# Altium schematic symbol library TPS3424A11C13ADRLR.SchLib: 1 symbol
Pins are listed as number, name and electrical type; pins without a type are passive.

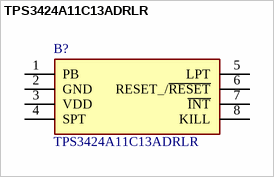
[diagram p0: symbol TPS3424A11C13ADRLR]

## TPS3424A11C13ADRLR
designator B?
Supervisory Circuits Nanopower push-button controller with programmable delay; Manufacturer_Name: Texas Instruments; Geometry.Height: 0.6mm
footprint SOTFL50P160X60-8N
pins: 1 PB, 2 GND, 3 VDD, 4 SPT, 5 LPT, 6 RESET_/~{RESET}, 7 ~{INT}, 8 KILL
